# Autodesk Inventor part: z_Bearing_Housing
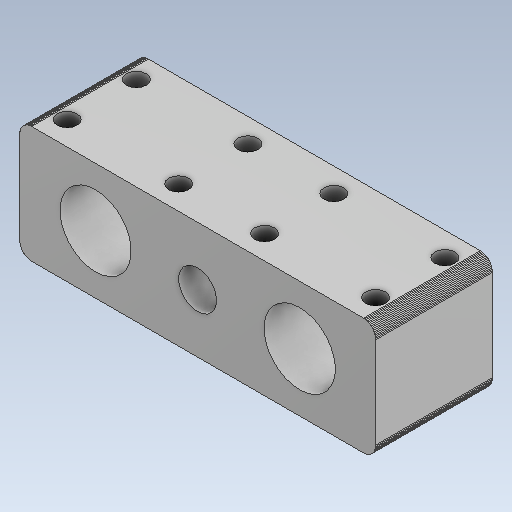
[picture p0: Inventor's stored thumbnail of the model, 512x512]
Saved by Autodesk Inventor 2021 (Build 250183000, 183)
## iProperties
Created: 2026-10
Part Number: z_Bearing_Housing
Material: Steel
Document SubType Name: Modeling
Designer: hp
Density: 7.85 g/cm^3
Appearance: Default
Author: hp
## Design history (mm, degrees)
feature "Body1"
body "Solid1"
